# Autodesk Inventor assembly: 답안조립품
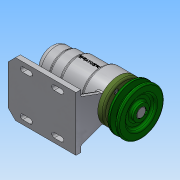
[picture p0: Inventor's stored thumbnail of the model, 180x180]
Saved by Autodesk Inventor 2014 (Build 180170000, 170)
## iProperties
Created: 2017-09
Part Number: 답안조립품
Document SubType Name: Assembly
Designer: NET
Author: NET
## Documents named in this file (12)
- C:\Users\NET\Desktop\470907V1009\답안조립품.iam
- C:\Users\NET\Desktop\470907V1009\본체.ipt
- C:\Users\NET\Desktop\470907V1009\축.ipt
- C:\Users\NET\Desktop\470907V1009\베어링 6004.ipt
- C:\Users\NET\Desktop\470907V1009\어댑터슬리브.ipt
- C:\Users\NET\Desktop\470907V1009\볼트 M4 x 12.ipt
- C:\Users\NET\Desktop\470907V1009\베어링 51202.ipt
- C:\Users\NET\Desktop\470907V1009\커버.ipt
- C:\Users\NET\Desktop\470907V1009\키 5 x 5 x 16.ipt
- C:\Users\NET\Desktop\470907V1009\V벨트풀리.ipt
- C:\Users\NET\Desktop\470907V1009\멈춤나사 M3x8.ipt
- C:\Users\NET\Desktop\470907V1009\오일 실 20x35x7.ipt
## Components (1 placed, 1 different names)
1. V벨트풀리:1
